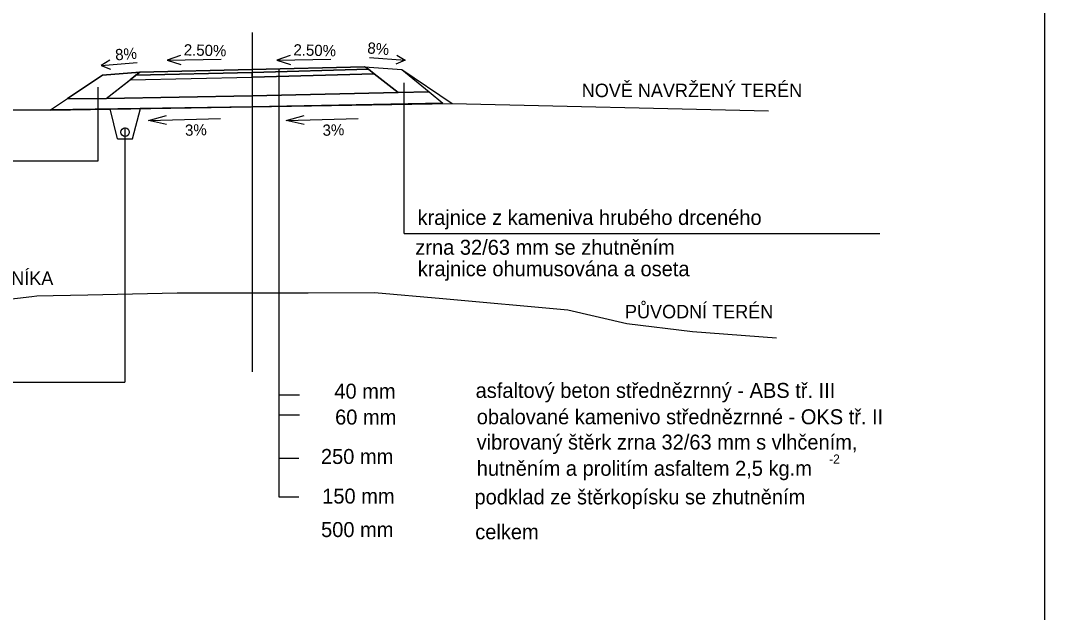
# Model space of a CAD drawing. Extents: x -553158.6 to -553137.6, y -1027695 to -1027665.3.
# Drawn here: x -553151.28 to -553137.61, y -1027687.13 to -1027679.22 of the extents above; entities that cross this region are included whole.
import ezdxf

# ---------------------------------------------------------------- set-up
doc = ezdxf.new("R2010")
doc.units = 0
for name, color, linetype in [('16', 7, 'Continuous'), ('60', 7, 'Continuous'), ('Implicitní', 7, 'Continuous'), ('POPIS', 7, 'Continuous'), ('TERÉN', 7, 'Continuous'), ('WORKING_LAYER', 7, 'Continuous')]:
    doc.layers.add(name, color=color, linetype=linetype)

# ---------------------------------------------------------------- blocks, each defined once
blk = doc.blocks.new('A$C038E1F8A')
at = {"layer": 'Implicitní'}
blk.add_line((0, 0.297), (0, 0), dxfattribs=at)

msp = doc.modelspace()

# ---------------------------------------------------------------- linework, layer by layer
for p, q in [((-553146.158, -1027682.068), (-553146.158, -1027680.058)), ((-553150.878, -1027680.424), (-553154.614, -1027680.424)), ((-553149.984, -1027680.806), (-553150.084, -1027680.406)), ((-553149.784, -1027680.806), (-553149.68, -1027680.398)), ((-553149.984, -1027680.806), (-553149.784, -1027680.806))]:
    msp.add_line(p, q)
for points in [[(-553150.878, -1027680.424), (-553150.878, -1027680.416), (-553150.653, -1027680.266), (-553150.188, -1027679.956), (-553149.688, -1027679.916), (-553148.188, -1027679.879), (-553146.688, -1027679.841), (-553146.188, -1027679.881), (-553145.52, -1027680.334)], [(-553150.878, -1027680.424), (-553145.52, -1027680.334), (-553141.294, -1027680.431)], [(-553155.188, -1027682.933), (-553153.625, -1027683.047), (-553152.816, -1027683.106), (-553151.128, -1027682.91), (-553151.063, -1027682.901), (-553150.844, -1027682.897), (-553150.384, -1027682.888), (-553149.19, -1027682.863), (-553147.44, -1027682.863), (-553146.554, -1027682.857), (-553145.643, -1027682.939), (-553143.976, -1027683.087), (-553143.187, -1027683.272), (-553142.31, -1027683.379), (-553141.188, -1027683.464)]]:
    msp.add_lwpolyline(points)
for points in [[(-553149.688, -1027679.916), (-553150.188, -1027679.956), (-553150.653, -1027680.266), (-553150.139, -1027680.266)], [(-553150.139, -1027680.266), (-553149.817, -1027680.016), (-553148.189, -1027679.979), (-553146.56, -1027679.935), (-553146.238, -1027680.185), (-553148.189, -1027680.229)], [(-553148.189, -1027679.919), (-553149.739, -1027679.956), (-553149.817, -1027680.016), (-553148.189, -1027679.979), (-553146.56, -1027679.935), (-553146.637, -1027679.875), (-553148.189, -1027679.919), (-553146.637, -1027679.875), (-553146.688, -1027679.841), (-553148.188, -1027679.879), (-553149.688, -1027679.916), (-553149.739, -1027679.956)], [(-553148.189, -1027679.919), (-553149.739, -1027679.956), (-553149.817, -1027680.016), (-553148.189, -1027679.979)], [(-553148.189, -1027679.919), (-553146.637, -1027679.875), (-553146.56, -1027679.935), (-553148.189, -1027679.979)], [(-553146.688, -1027679.841), (-553146.188, -1027679.881), (-553145.827, -1027680.179), (-553146.238, -1027680.185), (-553146.56, -1027679.935), (-553146.637, -1027679.875)], [(-553150.878, -1027680.416), (-553150.653, -1027680.266), (-553150.139, -1027680.266), (-553148.189, -1027680.229), (-553146.238, -1027680.185), (-553145.827, -1027680.179), (-553145.642, -1027680.329), (-553148.189, -1027680.379)]]:
    msp.add_lwpolyline(points, close=True)
at = {"layer": '60'}
msp.add_line((-553148.188, -1027679.384), (-553148.188, -1027683.916), dxfattribs=at)
at = {"layer": 'POPIS'}
for p, q in [((-553147.826, -1027685.592), (-553147.826, -1027679.872)), ((-553150.249, -1027680.114), (-553150.249, -1027681.105)), ((-553149.889, -1027680.652), (-553149.889, -1027684.053)), ((-553150.249, -1027681.105), (-553156.595, -1027681.105)), ((-553146.158, -1027682.068), (-553139.811, -1027682.068)), ((-553155.12, -1027684.053), (-553149.889, -1027684.053)), ((-553147.826, -1027684.225), (-553147.558, -1027684.225)), ((-553147.826, -1027684.49), (-553147.558, -1027684.49)), ((-553147.567, -1027685.076), (-553147.826, -1027685.076)), ((-553147.567, -1027685.592), (-553147.826, -1027685.592))]:
    msp.add_line(p, q, dxfattribs=at)
at = {"layer": 'WORKING_LAYER'}
for p, q in [((-553150.088, -1027679.756), (-553150.203, -1027679.825)), ((-553150.203, -1027679.825), (-553149.724, -1027679.787)), ((-553149.144, -1027679.692), (-553149.322, -1027679.756)), ((-553149.322, -1027679.756), (-553148.602, -1027679.739)), ((-553149.322, -1027679.756), (-553149.141, -1027679.812)), ((-553147.68, -1027679.692), (-553147.858, -1027679.756)), ((-553147.858, -1027679.756), (-553147.138, -1027679.739)), ((-553147.858, -1027679.756), (-553147.677, -1027679.812)), ((-553146.622, -1027679.717), (-553146.144, -1027679.756)), ((-553146.622, -1027679.717), (-553146.144, -1027679.756)), ((-553146.144, -1027679.756), (-553146.268, -1027679.806)), ((-553146.144, -1027679.756), (-553146.268, -1027679.806)), ((-553146.259, -1027679.686), (-553146.144, -1027679.756)), ((-553150.203, -1027679.825), (-553150.078, -1027679.875)), ((-553149.571, -1027680.562), (-553149.333, -1027680.495)), ((-553147.735, -1027680.562), (-553147.496, -1027680.495)), ((-553149.571, -1027680.562), (-553148.612, -1027680.533)), ((-553149.33, -1027680.615), (-553149.571, -1027680.562)), ((-553147.735, -1027680.562), (-553146.775, -1027680.533)), ((-553147.493, -1027680.615), (-553147.735, -1027680.562))]:
    msp.add_line(p, q, dxfattribs=at)
msp.add_circle((-553149.885, -1027680.716), 0.0562, dxfattribs=at)

# ---------------------------------------------------------------- block references
at = {"layer": 'Implicitní', "xscale": 100, "yscale": 100}
msp.add_blockref('A$C038E1F8A', (-553137.611, -1027695.038), dxfattribs=at)

# ---------------------------------------------------------------- texts
at = {"layer": '16'}
for p in [(-553149.103, -1027679.69), (-553147.639, -1027679.69)]:
    msp.add_text('2.50%', height=0.15, rotation=358.5679, dxfattribs=at).set_placement(p)
for s, p in [('NOVĚ NAVRŽENÝ TERÉN', (-553143.788, -1027680.248)), ('VIZ. SAMOSTATNÝ PROJEKT RYBNÍKA', (-553155.31, -1027682.756)), ('PŮVODNÍ TERÉN', (-553143.211, -1027683.202))]:
    msp.add_text(s, height=0.18, dxfattribs=at).set_placement(p)
at = {"layer": 'POPIS'}
for s, p in [('krajnice z kameniva hrubého drceného', (-553145.981, -1027681.955)), ('zrna 32/63 mm se zhutněním', (-553146.01, -1027682.353)), ('krajnice ohumusována a oseta', (-553145.977, -1027682.64)), ('podklad ze štěrkopísku se zhutněním', (-553145.22, -1027685.687)), ('celkem', (-553145.21, -1027686.153))]:
    msp.add_text(s, height=0.2, dxfattribs=at).set_placement(p)
at = {"layer": 'TERÉN'}
for s, height, p in [('asfaltový beton střednězrnný - ABS tř. III', 0.2, (-553145.205, -1027684.265)), ('40 mm', 0.2, (-553147.091, -1027684.275)), ('60 mm', 0.2, (-553147.081, -1027684.621)), ('obalované kamenivo střednězrnné - OKS tř. II', 0.2, (-553145.19, -1027684.617)), ('vibrovaný štěrk zrna 32/63 mm s vlhčením,', 0.2, (-553145.191, -1027684.955)), ('250 mm', 0.2, (-553147.27, -1027685.147)), ('hutněním a prolitím asfaltem 2,5 kg.m', 0.2, (-553145.19, -1027685.305)), ('-2', 0.12, (-553140.486, -1027685.141)), ('150 mm  ', 0.2, (-553147.253, -1027685.676)), ('500 mm  ', 0.2, (-553147.268, -1027686.123))]:
    msp.add_text(s, height=height, dxfattribs=at).set_placement(p)
at = {"layer": 'WORKING_LAYER'}
for s, rotation, p in [('8%', 355.4251, (-553146.655, -1027679.664)), ('8%', 4.5749, (-553150.011, -1027679.758)), ('3%', 1.7185, (-553149.082, -1027680.765)), ('3%', 1.7185, (-553147.246, -1027680.765))]:
    msp.add_text(s, height=0.15, rotation=rotation, dxfattribs=at).set_placement(p)

doc.saveas('drawing.dxf')
